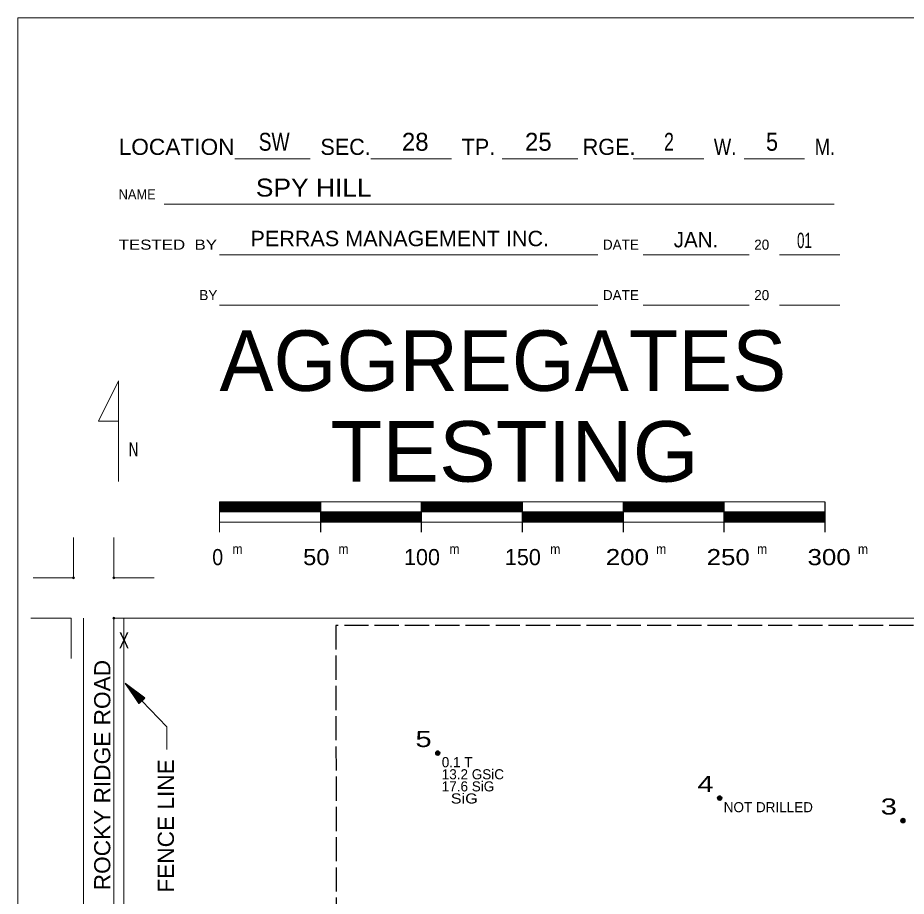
# Model space of a CAD drawing. Extents: x -496 to 480, y -450 to 700.
# Drawn here: x -450 to -9.7, y 264.4 to 700 of the extents above; entities that cross this region are included whole.
import ezdxf
from ezdxf.enums import TextEntityAlignment as Align

# ---------------------------------------------------------------- set-up
doc = ezdxf.new("R2010")
doc.units = 0
doc.header["$LTSCALE"] = 2
doc.header["$PDMODE"] = 32
doc.header["$PDSIZE"] = 1
doc.linetypes.add('LONG_DASHED', pattern=[7.5, 6, -1.5])
for name, color, linetype, lineweight in [('1', 7, 'Continuous', 13), ('2', 7, 'Continuous', 35), ('3', 7, 'Continuous', 13), ('4', 7, 'Continuous', 25)]:
    doc.layers.add(name, color=color, linetype=linetype, lineweight=lineweight)

msp = doc.modelspace()

# ---------------------------------------------------------------- linework, layer by layer
at = {"layer": '1'}
for p, q in [((-342.517, 629.973), (-305.017, 629.973)), ((-275.017, 629.973), (-235.017, 629.973)), ((-210.017, 629.973), (-172.517, 629.973)), ((-145.017, 629.973), (-110.017, 629.973)), ((-90.017, 629.973), (-60.017, 629.973)), ((-377.517, 607.473), (-45.359, 607.473)), ((-350.017, 582.473), (-162.517, 582.473)), ((-140.017, 582.473), (-87.517, 582.473)), ((-72.517, 582.473), (-42.517, 582.473)), ((-350.017, 557.473), (-162.517, 557.473)), ((-140.017, 557.473), (-87.517, 557.473)), ((-72.517, 557.473), (-42.517, 557.473)), ((-350.017, 459.973), (-350.017, 444.973)), ((-50.017, 459.973), (-350.017, 459.973)), ((-350.017, 454.973), (-50.017, 454.973)), ((-422.391, 422.339), (-422.391, 442.339)), ((-402.391, 422.339), (-402.391, 442.339)), ((-422.391, 422.339), (-442.391, 422.339)), ((-423.537, 402.339), (-443.537, 402.339)), ((-423.537, 402.339), (-423.537, 382.339)), ((-402.391, 402.339), (-402.391, -402.333)), ((-382.391, 402.339), (-402.391, 402.339))]:
    msp.add_line(p, q, dxfattribs=at)
at = {"layer": '1', "lineweight": 25}
for p, q in [((-350.017, 459.473), (-300.017, 459.473)), ((-350.017, 458.973), (-300.017, 458.973)), ((-350.017, 458.473), (-300.017, 458.473)), ((-350.017, 457.973), (-300.017, 457.973)), ((-300.017, 459.973), (-300.017, 444.973)), ((-250.017, 459.973), (-250.017, 444.973)), ((-250.017, 459.473), (-200.017, 459.473)), ((-250.017, 458.973), (-200.017, 458.973)), ((-250.017, 458.473), (-200.017, 458.473)), ((-250.017, 457.973), (-200.017, 457.973)), ((-200.017, 459.973), (-200.017, 444.973)), ((-150.017, 459.973), (-150.017, 444.973)), ((-150.017, 459.473), (-100.017, 459.473)), ((-150.017, 458.973), (-100.017, 458.973)), ((-150.017, 458.473), (-100.017, 458.473)), ((-150.017, 457.973), (-100.017, 457.973)), ((-100.017, 459.973), (-100.017, 444.973)), ((-50.017, 459.973), (-50.017, 444.973)), ((-350.017, 457.473), (-300.017, 457.473)), ((-350.017, 456.973), (-300.017, 456.973)), ((-350.017, 456.473), (-300.017, 456.473)), ((-350.017, 456.473), (-300.017, 456.473)), ((-350.017, 456.473), (-300.017, 456.473)), ((-350.017, 455.973), (-300.017, 455.973)), ((-350.017, 455.973), (-300.017, 455.973)), ((-350.017, 455.473), (-300.017, 455.473)), ((-300.017, 454.473), (-250.017, 454.473)), ((-300.017, 453.973), (-250.017, 453.973)), ((-250.017, 457.473), (-200.017, 457.473)), ((-250.017, 456.973), (-200.017, 456.973)), ((-250.017, 456.473), (-200.017, 456.473)), ((-250.017, 455.973), (-200.017, 455.973)), ((-250.017, 455.473), (-200.017, 455.473)), ((-200.017, 454.473), (-150.017, 454.473)), ((-200.017, 453.973), (-150.017, 453.973)), ((-150.017, 457.473), (-100.017, 457.473)), ((-150.017, 456.973), (-100.017, 456.973)), ((-150.017, 456.473), (-100.017, 456.473)), ((-150.017, 455.973), (-100.017, 455.973)), ((-150.017, 455.473), (-100.017, 455.473)), ((-100.017, 454.473), (-50.017, 454.473)), ((-100.017, 453.973), (-50.017, 453.973)), ((-300.017, 453.473), (-250.017, 453.473)), ((-300.017, 452.973), (-250.017, 452.973)), ((-300.017, 452.473), (-250.017, 452.473)), ((-300.017, 451.973), (-250.017, 451.973)), ((-300.017, 451.473), (-250.017, 451.473)), ((-300.017, 450.973), (-250.017, 450.973)), ((-300.017, 450.473), (-250.017, 450.473)), ((-200.017, 453.473), (-150.017, 453.473)), ((-200.017, 452.973), (-150.017, 452.973)), ((-200.017, 452.473), (-150.017, 452.473)), ((-200.017, 451.973), (-150.017, 451.973)), ((-200.017, 451.473), (-150.017, 451.473)), ((-200.017, 450.973), (-150.017, 450.973)), ((-200.017, 450.473), (-150.017, 450.473)), ((-100.017, 453.473), (-50.017, 453.473)), ((-100.017, 452.973), (-50.017, 452.973)), ((-100.017, 452.473), (-50.017, 452.473)), ((-100.017, 451.973), (-50.017, 451.973)), ((-100.017, 451.473), (-50.017, 451.473)), ((-100.017, 450.973), (-50.017, 450.973)), ((-100.017, 450.473), (-50.017, 450.473))]:
    msp.add_line(p, q, dxfattribs=at)
at = {"layer": '1'}
for points in [[(449.983, -450.027), (449.983, 399.973), (449.983, 699.973), (-450.017, 699.973), (-450.017, 49.973), (-450.017, -450.027)], [(-400.017, 469.973), (-400.017, 519.973), (-410.017, 499.973), (-400.017, 499.973)], [(-350.017, 449.973), (-50.017, 449.973), (-50.017, 459.973)], [(-402.391, 422.339), (-382.391, 422.339), (-402.391, 422.339)], [(402.281, -402.333), (402.281, 402.339), (-402.391, 402.339)]]:
    msp.add_lwpolyline(points, dxfattribs=at)
for p in [(-422.391, 422.339), (-402.391, 422.339), (-402.391, 402.339)]:
    msp.add_point(p, dxfattribs=at)
at = {"layer": '2', "linetype": 'LONG_DASHED', "lineweight": 25}
for p, q in [((398.852, 398.739), (-292.391, 398.739)), ((-292.391, 398.739), (-292.094, 182.712))]:
    msp.add_line(p, q, dxfattribs=at)
at = {"layer": '2'}
for centre in [(-241.875, 335.397), (-102.135, 313.083), (-11.304, 301.926)]:
    msp.add_circle(centre, 1, dxfattribs=at)
for points in [[(-241.886, 336.284), (-241.156, 335.88), (-241.004, 335.031), (-241.689, 334.503), (-242.498, 334.734), (-242.785, 335.492), (-242.538, 336.054), (-241.965, 336.222), (-241.291, 335.728), (-241.307, 334.986), (-241.824, 334.728), (-242.347, 334.897), (-242.571, 335.543), (-241.987, 336.009), (-241.549, 335.475), (-241.588, 334.992), (-242.217, 335.127), (-242.071, 335.762), (-241.779, 335.211)], [(-102.146, 313.97), (-101.416, 313.566), (-101.264, 312.717), (-101.949, 312.189), (-102.758, 312.42), (-103.045, 313.178), (-102.798, 313.74), (-102.225, 313.908), (-101.551, 313.414), (-101.567, 312.672), (-102.084, 312.414), (-102.607, 312.583), (-102.831, 313.229), (-102.247, 313.695), (-101.809, 313.161), (-101.848, 312.678), (-102.477, 312.813), (-102.331, 313.448), (-102.039, 312.897)], [(-11.315, 302.813), (-10.585, 302.409), (-10.433, 301.56), (-11.118, 301.032), (-11.927, 301.263), (-12.214, 302.021), (-11.967, 302.583), (-11.394, 302.751), (-10.72, 302.257), (-10.736, 301.515), (-11.253, 301.257), (-11.776, 301.426), (-12, 302.072), (-11.416, 302.538), (-10.978, 302.004), (-11.017, 301.521), (-11.646, 301.656), (-11.5, 302.291), (-11.208, 301.74)]]:
    msp.add_spline(points, degree=3, dxfattribs=at)
at = {"layer": '3'}
for p, q in [((-417.391, 402.339), (-417.391, -402.333)), ((-397.391, 402.339), (-397.391, -402.333))]:
    msp.add_line(p, q, dxfattribs=at)
at = {"layer": '4', "lineweight": 13}
msp.add_lwpolyline([(-376.064, 337.144), (-376.064, 348.382), (-396.765, 369.959)], dxfattribs=at)
at = {"layer": '4'}
msp.add_lwpolyline([(-396.765, 369.959), (-389.901, 359.915), (-387.014, 362.684)], close=True, dxfattribs=at)
msp.add_lwpolyline([(-389.883, 360.068), (-396.369, 369.544), (-387.246, 362.688), (-389.788, 360.22), (-395.859, 369.013), (-387.504, 362.71), (-389.798, 360.448), (-395.32, 368.451), (-387.796, 362.699), (-389.733, 360.69), (-394.723, 367.798), (-388.101, 362.737), (-389.726, 360.998), (-394.005, 367.017), (-388.423, 362.698), (-389.688, 361.333), (-393.228, 366.177), (-388.851, 362.675), (-389.697, 361.684), (-392.405, 365.226), (-389.277, 362.745), (-389.735, 362.097), (-391.358, 364.164), (-389.811, 362.772)], dxfattribs=at)

# ---------------------------------------------------------------- texts
at = {"layer": '1'}
for s, height, width, p in [('SW', 8.89, 0.8, (-322.943, 634.038)), ('2', 8.89, 0.75, (-127.28, 634.037)), ('5', 8.89, 0.9, (-76.181, 634.038)), ('SPY HILL', 8.89, 1.1, (-303.323, 611.329)), ('PERRAS MANAGEMENT INC.', 7.62, 1.05, (-260.682, 586.728)), ('01', 7.62, 0.65, (-60.119, 585.781))]:
    msp.add_text(s, height=height, dxfattribs=dict(at, width=width)).set_placement(p, align=Align.CENTER)
for s, height, p in [('28', 8.89, (-253.021, 634.038)), ('25', 8.89, (-192.027, 634.038)), ('JAN.', 7.62, (-113.875, 586.148))]:
    msp.add_text(s, height=height, dxfattribs=at).set_placement(p, align=Align.CENTER)
for s, height, width, p in [('LOCATION', 8, 1.05, (-400.017, 631.973)), ('W.', 8, 0.85, (-105.017, 631.973)), ('M.', 8, 0.85, (-55.017, 631.973)), ('NAME', 5, 0.95, (-400.017, 609.973)), ('TESTED  BY', 5, 1.25, (-400.017, 584.973)), ('TESTING', 30, 1.05, (-295.017, 469.973)), ('N', 7, 0.7, (-395.017, 482.473)), ('0', 8, 0.9, (-353.607, 428.573)), ('m', 5, 0.9, (-343.607, 434.073)), ('50', 8, 1.1, (-308.607, 428.573)), ('m', 5, 0.9, (-291.107, 434.073)), ('m', 5, 0.9, (-236.107, 434.073)), ('m', 5, 0.9, (-186.107, 434.073)), ('200', 8, 1.2, (-158.607, 428.573)), ('m', 5, 0.9, (-133.607, 434.073)), ('250', 8, 1.2, (-108.607, 428.573)), ('m', 5, 0.9, (-83.607, 434.073)), ('300', 8, 1.2, (-58.607, 428.573)), ('m', 5, 0.9, (-33.607, 434.073))]:
    msp.add_text(s, height=height, dxfattribs=dict(at, width=width)).set_placement(p)
for s, height, p in [('SEC.', 8, (-300.017, 631.973)), ('TP.', 8, (-230.017, 631.973)), ('RGE.', 8, (-170.017, 631.973)), ('DATE', 5, (-160.017, 584.973)), ('20', 5, (-85.017, 584.973)), ('BY', 5, (-360.017, 559.973)), ('DATE', 5, (-160.017, 559.973)), ('20', 5, (-85.017, 559.973)), ('AGGREGATES', 30, (-350.017, 514.973)), ('100', 8, (-258.607, 428.573)), ('150', 8, (-208.607, 428.573))]:
    msp.add_text(s, height=height, dxfattribs=at).set_placement(p)
at = {"layer": '2', "width": 1.35}
for s, p in [('  5', (-244.876, 338.397)), ('  4', (-105.136, 316.083)), ('  3', (-14.305, 304.926))]:
    msp.add_text(s, height=8, dxfattribs=at).set_placement(p, align=Align.RIGHT)
at = {"layer": '2'}
for s, p in [('0.1 T      ', (-239.875, 328.397)), ('13.2 GSiC  ', (-239.875, 322.397)), ('17.6 SiG   ', (-239.875, 316.397)), ('NOT DRILLED', (-100.135, 306.083))]:
    msp.add_text(s, height=5, dxfattribs=at).set_placement(p)
at = {"layer": '2', "width": 1.2}
msp.add_text('  SiG      ', height=5, dxfattribs=at).set_placement((-239.875, 310.397))
at = {"layer": '3', "width": 0.7}
msp.add_text('X', height=8, dxfattribs=at).set_placement((-397.37, 387.272), align=Align.CENTER)
at = {"layer": '4', "width": 1.05}
for s, p in [('ROCKY RIDGE ROAD', (-404.154, 324.479)), ('FENCE LINE', (-372.628, 299.279))]:
    msp.add_text(s, height=8, rotation=90, dxfattribs=at).set_placement(p, align=Align.CENTER)

doc.saveas('drawing.dxf')
